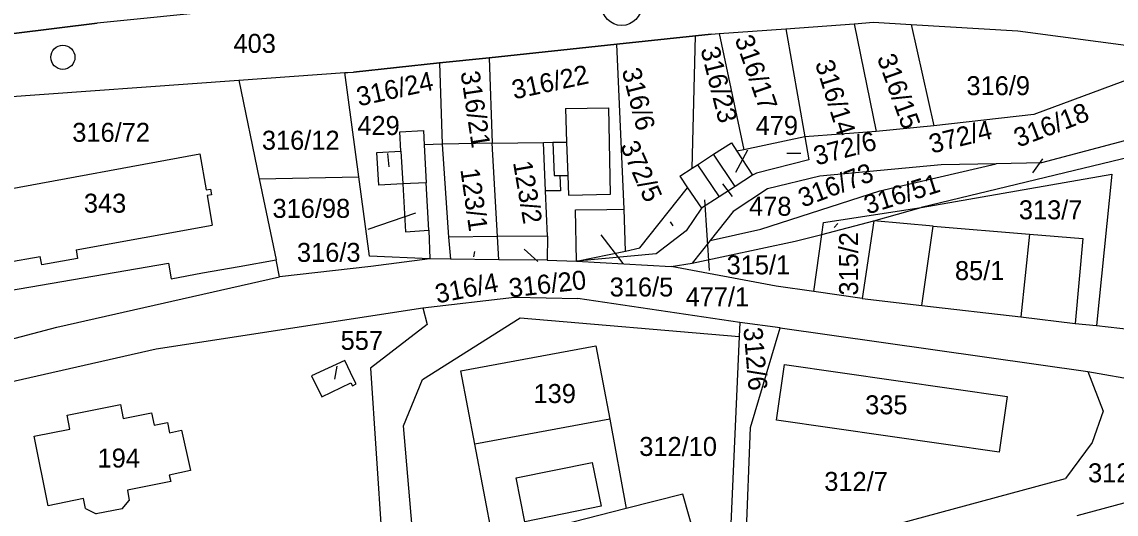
# Model space of a CAD drawing. Extents: x -805826 to -803822, y -1165880 to -1164382.
# Drawn here: x -805597.3 to -805401.4, y -1164975.4 to -1164887.3 of the extents above; entities that cross this region are included whole.
import ezdxf

# ---------------------------------------------------------------- set-up
doc = ezdxf.new("R2010")
doc.units = 0
for name, color, linetype in [('kilometráž - 2880', 7, 'Continuous'), ('kn_celek - Cisla parcel pomocna', 7, 'Continuous'), ('kn_celek - Cisla pozemkovych parcel', 7, 'Continuous'), ('kn_celek - Cisla stavebnich parcel', 7, 'Continuous'), ('kn_celek - Hranice parcel', 7, 'Continuous'), ('kn_celek - Vnitrni kresby', 7, 'Continuous'), ('plochy - SZDC', 7, 'Continuous')]:
    doc.layers.add(name, color=color, linetype=linetype)

msp = doc.modelspace()

# ---------------------------------------------------------------- linework, layer by layer
at = {"layer": 'kilometráž - 2880'}
for centre, radius in [((-805489.96, -1164884.32), 3.59), ((-805590, -1164893.62), 2.16)]:
    msp.add_circle(centre, radius, dxfattribs=at)
at = {"layer": 'kn_celek - Cisla parcel pomocna'}
for p, q in [((-805531.61, -1164913.22), (-805531.8, -1164910.83)), ((-805469.54, -1164914.21), (-805467.39, -1164910.18)), ((-805460.42, -1164910.79), (-805457.91, -1164910.82)), ((-805416.36, -1164914.29), (-805414.58, -1164911.83)), ((-805471.9, -1164916.3), (-805470.18, -1164918.54)), ((-805475.12, -1164919.13), (-805474.29, -1164931.81)), ((-805526.88, -1164921.56), (-805535.43, -1164924.44)), ((-805480.72, -1164923.78), (-805481.24, -1164923.09)), ((-805451.93, -1164924.09), (-805451.29, -1164923.41)), ((-805493.68, -1164925.42), (-805489.74, -1164930.54)), ((-805516.28, -1164928.41), (-805516.51, -1164929.36)), ((-805507.41, -1164927.97), (-805504.99, -1164930.21)), ((-805541.34, -1164951.29), (-805540.87, -1164948.96))]:
    msp.add_line(p, q, dxfattribs=at)
at = {"layer": 'kn_celek - Hranice parcel'}
for p, q in [((-805510.27, -1164880.08), (-805583.88, -1164887.5)), ((-805598.76, -1164889.34), (-805583.88, -1164887.5)), ((-805472.49, -1164889.38), (-805460.55, -1164888.5)), ((-805460.55, -1164888.5), (-805448.37, -1164887.6)), ((-805460.55, -1164888.5), (-805457.17, -1164907.89)), ((-805448.37, -1164887.6), (-805444.88, -1164887.35)), ((-805448.37, -1164887.6), (-805444.38, -1164906.91)), ((-805444.88, -1164887.35), (-805438.15, -1164887.74)), ((-805438.15, -1164887.74), (-805419.07, -1164888.85)), ((-805438.15, -1164887.74), (-805434.06, -1164905.91)), ((-805476.75, -1164889.78), (-805490.82, -1164891.27)), ((-805477.35, -1164913.47), (-805476.75, -1164889.78)), ((-805473.96, -1164889.48), (-805476.75, -1164889.78)), ((-805473.96, -1164889.48), (-805472.49, -1164889.38)), ((-805472.49, -1164889.38), (-805468.11, -1164910.19)), ((-805419.07, -1164888.85), (-805387.24, -1164893.09)), ((-805490.82, -1164891.27), (-805513.67, -1164893.69)), ((-805489.49, -1164920.82), (-805490.82, -1164891.27)), ((-805513.67, -1164893.69), (-805522.59, -1164894.64)), ((-805513.67, -1164893.69), (-805513.17, -1164909.01)), ((-805387.24, -1164893.09), (-805416.15, -1164903.86)), ((-805558.51, -1164897.74), (-805539.54, -1164896.37)), ((-805539.54, -1164896.37), (-805539, -1164896.34)), ((-805537.03, -1164915), (-805539.54, -1164896.37)), ((-805539, -1164896.34), (-805537.96, -1164896.27)), ((-805522.59, -1164894.64), (-805537.96, -1164896.27)), ((-805522.59, -1164894.64), (-805522.1, -1164909.19)), ((-805603.43, -1164900.95), (-805558.51, -1164897.74)), ((-805558.51, -1164897.74), (-805554.85, -1164915.37)), ((-805500.03, -1164902.77), (-805492.27, -1164902.67)), ((-805500.03, -1164902.77), (-805499.83, -1164908.8)), ((-805491.94, -1164918.16), (-805492.27, -1164902.67)), ((-805416.15, -1164903.86), (-805434.06, -1164905.91)), ((-805434.06, -1164905.91), (-805444.38, -1164906.91)), ((-805529.66, -1164906.98), (-805525.45, -1164906.76)), ((-805529.48, -1164910.45), (-805529.66, -1164906.98)), ((-805525.45, -1164906.76), (-805525.31, -1164909.28)), ((-805457.17, -1164907.89), (-805468.11, -1164910.19)), ((-805444.38, -1164906.91), (-805457.17, -1164907.89)), ((-805457.17, -1164907.89), (-805456.45, -1164911.96)), ((-805395.26, -1164907.31), (-805414.79, -1164912.55)), ((-805522.1, -1164909.19), (-805525.31, -1164909.28)), ((-805513.17, -1164909.01), (-805522.1, -1164909.19)), ((-805513.17, -1164909.01), (-805503.95, -1164908.86)), ((-805512.2, -1164925.7), (-805513.17, -1164909.01)), ((-805503.95, -1164908.86), (-805502.28, -1164908.84)), ((-805502.28, -1164908.84), (-805499.83, -1164908.8)), ((-805473.5, -1164910.98), (-805470.33, -1164908.92)), ((-805470.33, -1164908.92), (-805469.34, -1164910.45)), ((-805602.56, -1164917.72), (-805565.5, -1164910.92)), ((-805565.5, -1164910.92), (-805564.36, -1164917.38)), ((-805533.81, -1164910.67), (-805529.48, -1164910.45)), ((-805533.45, -1164916.54), (-805533.81, -1164910.67)), ((-805529.48, -1164910.45), (-805529.12, -1164916.31)), ((-805476.4, -1164912.87), (-805473.5, -1164910.98)), ((-805469.62, -1164916.74), (-805473.5, -1164910.98)), ((-805468.11, -1164910.19), (-805469.34, -1164910.45)), ((-805469.34, -1164910.45), (-805466.56, -1164914.75)), ((-805456.45, -1164911.96), (-805465.84, -1164914.39)), ((-805395.24, -1164910.56), (-805436.32, -1164920.55)), ((-805479.57, -1164914.92), (-805477.35, -1164913.47)), ((-805477.35, -1164913.47), (-805476.4, -1164912.87)), ((-805476.4, -1164912.87), (-805472.52, -1164918.61)), ((-805432.74, -1164912.86), (-805454.5, -1164914.91)), ((-805443.76, -1164917.56), (-805422.95, -1164912.69)), ((-805422.95, -1164912.69), (-805432.74, -1164912.86)), ((-805414.79, -1164912.55), (-805422.95, -1164912.69)), ((-805554.85, -1164915.37), (-805537.03, -1164915)), ((-805554.85, -1164915.37), (-805551.83, -1164929.91)), ((-805535.1, -1164929.23), (-805537.03, -1164915)), ((-805501.01, -1164914.8), (-805499.62, -1164914.77)), ((-805501.01, -1164914.8), (-805500.93, -1164917.55)), ((-805499.62, -1164914.77), (-805499.51, -1164918.3)), ((-805479.57, -1164914.92), (-805478.17, -1164917)), ((-805466.56, -1164914.75), (-805469.62, -1164916.74)), ((-805465.84, -1164914.39), (-805466.56, -1164914.75)), ((-805454.5, -1164914.91), (-805463.85, -1164917.16)), ((-805436.32, -1164920.55), (-805402.19, -1164914.55)), ((-805402.19, -1164914.55), (-805404.99, -1164941.68)), ((-805564.36, -1164917.38), (-805563.55, -1164917.24)), ((-805563.55, -1164917.24), (-805563.38, -1164918.25)), ((-805529.12, -1164916.31), (-805533.45, -1164916.54)), ((-805524.95, -1164916.09), (-805529.12, -1164916.31)), ((-805529.12, -1164916.31), (-805528.65, -1164924.87)), ((-805524.47, -1164924.57), (-805524.95, -1164916.09)), ((-805500.93, -1164917.55), (-805503.58, -1164917.56)), ((-805503.25, -1164925.65), (-805503.58, -1164917.56)), ((-805486.7, -1164927.76), (-805478.17, -1164917)), ((-805478.17, -1164917), (-805475.7, -1164920.67)), ((-805469.62, -1164916.74), (-805472.52, -1164918.61)), ((-805463.85, -1164917.16), (-805470, -1164921.25)), ((-805465.04, -1164924.39), (-805443.76, -1164917.56)), ((-805563.38, -1164918.25), (-805564.18, -1164918.4)), ((-805564.18, -1164918.4), (-805563.26, -1164923.69)), ((-805499.51, -1164918.3), (-805491.94, -1164918.16)), ((-805472.52, -1164918.61), (-805475.7, -1164920.67)), ((-805498.23, -1164920.96), (-805492.6, -1164920.87)), ((-805498.02, -1164930.12), (-805498.23, -1164920.96)), ((-805492.6, -1164920.87), (-805489.49, -1164920.82)), ((-805489.26, -1164928.33), (-805489.49, -1164920.82)), ((-805475.7, -1164920.67), (-805478.4, -1164924.7)), ((-805470, -1164921.25), (-805474.14, -1164926.46)), ((-805453.84, -1164923.23), (-805436.32, -1164920.55)), ((-805444.83, -1164922.92), (-805436.32, -1164920.55)), ((-805587.63, -1164928.1), (-805563.26, -1164923.69)), ((-805454.11, -1164925.34), (-805444.83, -1164922.92)), ((-805454.11, -1164925.34), (-805453.84, -1164923.23)), ((-805444.83, -1164922.92), (-805446.92, -1164936.83)), ((-805434.2, -1164923.87), (-805444.83, -1164922.92)), ((-805528.65, -1164924.87), (-805524.47, -1164924.57)), ((-805524.47, -1164924.57), (-805524.3, -1164929.72)), ((-805512.2, -1164925.7), (-805520.94, -1164925.85)), ((-805503.25, -1164925.65), (-805512.2, -1164925.7)), ((-805511.96, -1164929.89), (-805512.2, -1164925.7)), ((-805503.25, -1164925.65), (-805503.3, -1164929.97)), ((-805478.4, -1164924.7), (-805483.78, -1164928.8)), ((-805474.14, -1164926.46), (-805465.04, -1164924.39)), ((-805458.88, -1164926.56), (-805454.11, -1164925.34)), ((-805455.59, -1164935.56), (-805454.11, -1164925.34)), ((-805434.2, -1164923.87), (-805416.93, -1164925.29)), ((-805416.93, -1164925.29), (-805407.43, -1164926.07)), ((-805520.94, -1164925.85), (-805520.59, -1164929.77)), ((-805474.14, -1164926.46), (-805477.33, -1164930.49)), ((-805477.33, -1164930.49), (-805458.88, -1164926.56)), ((-805407.43, -1164926.07), (-805408.76, -1164941.27)), ((-805600.23, -1164930.39), (-805594.07, -1164929.29)), ((-805593.77, -1164930.81), (-805594.07, -1164929.29)), ((-805587.35, -1164929.64), (-805593.77, -1164930.81)), ((-805587.63, -1164928.1), (-805587.35, -1164929.64)), ((-805524.3, -1164929.72), (-805535.1, -1164929.23)), ((-805498.02, -1164930.12), (-805489.26, -1164928.33)), ((-805483.78, -1164928.8), (-805498.02, -1164930.12)), ((-805489.26, -1164928.33), (-805486.7, -1164927.76)), ((-805603.99, -1164936.15), (-805571.11, -1164930.48)), ((-805571.11, -1164930.48), (-805570.64, -1164933.27)), ((-805565, -1164932.2), (-805558.45, -1164931.06)), ((-805558.45, -1164931.06), (-805551.83, -1164929.91)), ((-805551.2, -1164932.92), (-805551.83, -1164929.91)), ((-805534.87, -1164931.11), (-805551.2, -1164932.92)), ((-805524.3, -1164929.72), (-805534.87, -1164931.11)), ((-805520.59, -1164929.77), (-805524.3, -1164929.72)), ((-805511.96, -1164929.89), (-805520.59, -1164929.77)), ((-805503.3, -1164929.97), (-805511.96, -1164929.89)), ((-805503.3, -1164929.97), (-805498.02, -1164930.12)), ((-805498.02, -1164930.12), (-805481.12, -1164931.09)), ((-805481.12, -1164931.09), (-805477.33, -1164930.49)), ((-805462.32, -1164934.64), (-805481.12, -1164931.09)), ((-805591.1, -1164941.97), (-805551.2, -1164932.92)), ((-805570.64, -1164933.27), (-805565, -1164932.2)), ((-805455.59, -1164935.56), (-805462.32, -1164934.64)), ((-805446.92, -1164936.83), (-805455.59, -1164935.56)), ((-805525.55, -1164938.51), (-805509.17, -1164936.56)), ((-805509.17, -1164936.56), (-805497.81, -1164936.83)), ((-805468.79, -1164941.13), (-805497.81, -1164936.83)), ((-805446.92, -1164936.83), (-805436.23, -1164938.05)), ((-805573.28, -1164945.86), (-805525.55, -1164938.51)), ((-805525.55, -1164938.51), (-805524.81, -1164941.5)), ((-805436.23, -1164938.05), (-805418.49, -1164940.1)), ((-805525.59, -1164951.32), (-805508.16, -1164940.3)), ((-805508.16, -1164940.3), (-805468.91, -1164943.64)), ((-805468.79, -1164941.13), (-805468.91, -1164943.64)), ((-805461.59, -1164942.09), (-805468.79, -1164941.13)), ((-805418.49, -1164940.1), (-805408.76, -1164941.27)), ((-805408.76, -1164941.27), (-805404.99, -1164941.68)), ((-805618.93, -1164949.3), (-805591.1, -1164941.97)), ((-805524.81, -1164941.5), (-805534.95, -1164949.29)), ((-805466.91, -1164959.9), (-805461.59, -1164942.09)), ((-805461.59, -1164942.09), (-805406.54, -1164949.88)), ((-805404.99, -1164941.68), (-805398.7, -1164942.36)), ((-805518.74, -1164949.76), (-805494.58, -1164945.31)), ((-805494.58, -1164945.31), (-805492.1, -1164958.46)), ((-805468.91, -1164943.64), (-805470.61, -1164981.43)), ((-805606.33, -1164953.3), (-805573.28, -1164945.86)), ((-805539.55, -1164947.92), (-805545.5, -1164950.68)), ((-805537.95, -1164951.23), (-805539.55, -1164947.92)), ((-805462.23, -1164958.64), (-805460.79, -1164948.66)), ((-805460.79, -1164948.66), (-805420.97, -1164954.36)), ((-805545.5, -1164950.68), (-805543.65, -1164954.44)), ((-805537.48, -1164952.1), (-805537.95, -1164951.23)), ((-805534.95, -1164949.29), (-805532.02, -1164993.45)), ((-805516.26, -1164962.92), (-805518.74, -1164949.76)), ((-805406.54, -1164949.88), (-805403.74, -1164956.97)), ((-805406.54, -1164949.88), (-805390.87, -1164952.7)), ((-805543.65, -1164954.44), (-805538.47, -1164951.9)), ((-805538.47, -1164951.9), (-805538.15, -1164952.49)), ((-805538.15, -1164952.49), (-805537.48, -1164952.1)), ((-805529.03, -1164959.6), (-805525.59, -1164951.32)), ((-805420.97, -1164954.36), (-805422.39, -1164964.33)), ((-805589.25, -1164957.72), (-805579.71, -1164955.8)), ((-805579.71, -1164955.8), (-805579.2, -1164958.29)), ((-805403.74, -1164956.97), (-805405.75, -1164962.6)), ((-805588.75, -1164960.21), (-805589.25, -1164957.72)), ((-805579.2, -1164958.29), (-805574.12, -1164957.27)), ((-805574.12, -1164957.27), (-805573.68, -1164959.48)), ((-805573.68, -1164959.48), (-805571.26, -1164959)), ((-805571.26, -1164959), (-805570.89, -1164960.88)), ((-805492.1, -1164958.46), (-805489.17, -1164974.45)), ((-805422.39, -1164964.33), (-805462.23, -1164958.64)), ((-805595.16, -1164961.5), (-805588.75, -1164960.21)), ((-805570.89, -1164960.88), (-805568.75, -1164960.42)), ((-805568.75, -1164960.42), (-805567.13, -1164967.6)), ((-805526.2, -1164992.2), (-805529.03, -1164959.6)), ((-805467.86, -1164984.54), (-805466.91, -1164959.9)), ((-805592.63, -1164973.95), (-805595.16, -1164961.5)), ((-805512.48, -1164982.77), (-805516.26, -1164962.92)), ((-805405.75, -1164962.6), (-805410.52, -1164969.05)), ((-805567.13, -1164967.6), (-805570.95, -1164968.44)), ((-805570.95, -1164968.44), (-805570.66, -1164969.58)), ((-805570.66, -1164969.58), (-805578.43, -1164971.14)), ((-805467.86, -1164984.54), (-805410.52, -1164969.05)), ((-805586.33, -1164972.65), (-805592.63, -1164973.95)), ((-805585.95, -1164974.41), (-805586.33, -1164972.65)), ((-805578.43, -1164971.14), (-805578.12, -1164972.98)), ((-805479.02, -1164971.86), (-805489.17, -1164974.45)), ((-805475.98, -1164982.47), (-805479.02, -1164971.86)), ((-805585.95, -1164974.41), (-805584.04, -1164975.36)), ((-805579.41, -1164974.5), (-805584.04, -1164975.36)), ((-805579.41, -1164974.5), (-805578.12, -1164972.98)), ((-805489.17, -1164974.45), (-805508.02, -1164979.27)), ((-805408.45, -1164975.7), (-805398.47, -1164973.02))]:
    msp.add_line(p, q, dxfattribs=at)
at = {"layer": 'kn_celek - Vnitrni kresby'}
for p, q in [((-805525.31, -1164909.28), (-805524.95, -1164916.09)), ((-805522.1, -1164909.19), (-805520.94, -1164925.85)), ((-805503.58, -1164917.56), (-805503.95, -1164908.86)), ((-805502.28, -1164908.84), (-805502.05, -1164914.81)), ((-805499.83, -1164908.8), (-805499.62, -1164914.77)), ((-805502.05, -1164914.81), (-805501.01, -1164914.8)), ((-805436.23, -1164938.05), (-805434.2, -1164923.87)), ((-805416.93, -1164925.29), (-805418.49, -1164940.1)), ((-805492.1, -1164958.46), (-805516.26, -1164962.92)), ((-805508.87, -1164968.94), (-805495.24, -1164966.18)), ((-805495.24, -1164966.18), (-805493.65, -1164974.03)), ((-805507.27, -1164976.8), (-805508.87, -1164968.94)), ((-805493.65, -1164974.03), (-805507.27, -1164976.8))]:
    msp.add_line(p, q, dxfattribs=at)
at = {"layer": 'plochy - SZDC'}
for p, q in [((-805510.27, -1164880.08), (-805583.88, -1164887.5)), ((-805583.88, -1164887.5), (-805598.76, -1164889.34)), ((-805472.49, -1164889.38), (-805460.55, -1164888.5)), ((-805460.55, -1164888.5), (-805448.37, -1164887.6)), ((-805448.37, -1164887.6), (-805444.88, -1164887.35)), ((-805444.88, -1164887.35), (-805438.15, -1164887.74)), ((-805438.15, -1164887.74), (-805419.07, -1164888.85)), ((-805490.82, -1164891.27), (-805476.75, -1164889.78)), ((-805476.75, -1164889.78), (-805473.96, -1164889.48)), ((-805473.96, -1164889.48), (-805472.49, -1164889.38)), ((-805419.07, -1164888.85), (-805387.24, -1164893.09)), ((-805513.67, -1164893.69), (-805490.82, -1164891.27)), ((-805522.59, -1164894.64), (-805513.67, -1164893.69)), ((-805558.51, -1164897.74), (-805539.54, -1164896.37)), ((-805539.54, -1164896.37), (-805539, -1164896.34)), ((-805539, -1164896.34), (-805537.96, -1164896.27)), ((-805537.96, -1164896.27), (-805522.59, -1164894.64)), ((-805603.43, -1164900.95), (-805558.51, -1164897.74))]:
    msp.add_line(p, q, dxfattribs=at)

# ---------------------------------------------------------------- texts
at = {"layer": 'kn_celek - Cisla parcel pomocna'}
for s, rotation, p in [('316/18', 21.024, (-805418.95, -1164909.81)), ('372/6', 14.841, (-805455.08, -1164913.01)), ('372/5', 293.868, (-805490.29, -1164909.47)), ('316/51', 17.415, (-805445.95, -1164921.79)), ('316/4', 11.115, (-805523, -1164937.72)), ('316/20', 6.417, (-805509.98, -1164936.66))]:
    msp.add_text(s, height=3.4, rotation=rotation, dxfattribs=at).set_placement(p)
for s, p in [('429', (-805537.28, -1164907.54)), ('479', (-805465.98, -1164907.53)), ('478', (-805467.15, -1164922)), ('316/3', (-805548.09, -1164930.26)), ('316/5', (-805492.11, -1164936.46)), ('477/1', (-805478.52, -1164938.21)), ('557', (-805540.27, -1164946.02))]:
    msp.add_text(s, height=3.4, dxfattribs=at).set_placement(p)
at = {"layer": 'kn_celek - Cisla pozemkovych parcel'}
for s, height, p in [('403', 3.4, (-805559.45, -1164892.83)), ('316/9', 3.4, (-805428.24, -1164900.4)), ('316/72', 3.4, (-805588.31, -1164908.76)), ('316/12', 3.4, (-805554.37, -1164910.17)), ('372/6', 0.005, (-805460.42, -1164910.79)), ('316/18', 0.005, (-805416.36, -1164914.29)), ('316/98', 3.4, (-805552.47, -1164922.38)), ('313/7', 3.4, (-805418.86, -1164922.63)), ('316/3', 0.005, (-805526.88, -1164921.56)), ('372/5', 0.005, (-805480.72, -1164923.78)), ('316/5', 0.005, (-805493.68, -1164925.42)), ('316/51', 0.005, (-805451.93, -1164924.09)), ('316/4', 0.005, (-805516.28, -1164928.41)), ('316/20', 0.005, (-805507.41, -1164927.97)), ('315/1', 3.4, (-805471.18, -1164932.5)), ('312/10', 3.4, (-805486.81, -1164965.02)), ('312/11', 3.4, (-805406.47, -1164969.74)), ('312/7', 3.4, (-805453.69, -1164971.28))]:
    msp.add_text(s, height=height, dxfattribs=at).set_placement(p)
for s, rotation, p in [('316/17', 289.233, (-805469.77, -1164890.31)), ('316/23', 284.013, (-805475.87, -1164892.15)), ('316/14', 287.28, (-805455.38, -1164894.68)), ('316/15', 289.8, (-805444.3, -1164893.7)), ('316/24', 12.429, (-805537.02, -1164902.42)), ('316/21', 278.514, (-805518.82, -1164896.28)), ('316/22', 12.15, (-805509.23, -1164901.17)), ('316/6', 284.076, (-805489.96, -1164895.96)), ('372/4', 14.094, (-805434.45, -1164910.88)), ('316/73', 20.853, (-805457.56, -1164920.57)), ('315/2', 90.009, (-805447.64, -1164936.3)), ('312/6', 274.905, (-805468.17, -1164942.1))]:
    msp.add_text(s, height=3.4, rotation=rotation, dxfattribs=at).set_placement(p)
at = {"layer": 'kn_celek - Cisla stavebnich parcel'}
for s, height, p in [('429', 0.005, (-805531.61, -1164913.22)), ('479', 0.005, (-805469.54, -1164914.21)), ('478', 0.005, (-805471.9, -1164916.3)), ('343', 3.4, (-805586.24, -1164921.45)), ('477/1', 0.005, (-805475.12, -1164919.13)), ('85/1', 3.4, (-805430.3, -1164933.52)), ('557', 0.005, (-805541.34, -1164951.29)), ('139', 3.4, (-805505.74, -1164955.54)), ('335', 3.4, (-805446.37, -1164957.56)), ('194', 3.4, (-805583.79, -1164967.1))]:
    msp.add_text(s, height=height, dxfattribs=at).set_placement(p)
for s, rotation, p in [('123/1', 278.055, (-805518.85, -1164913.7)), ('123/2', 279.72, (-805509.43, -1164912.44))]:
    msp.add_text(s, height=3.4, rotation=rotation, dxfattribs=at).set_placement(p)

doc.saveas('drawing.dxf')
